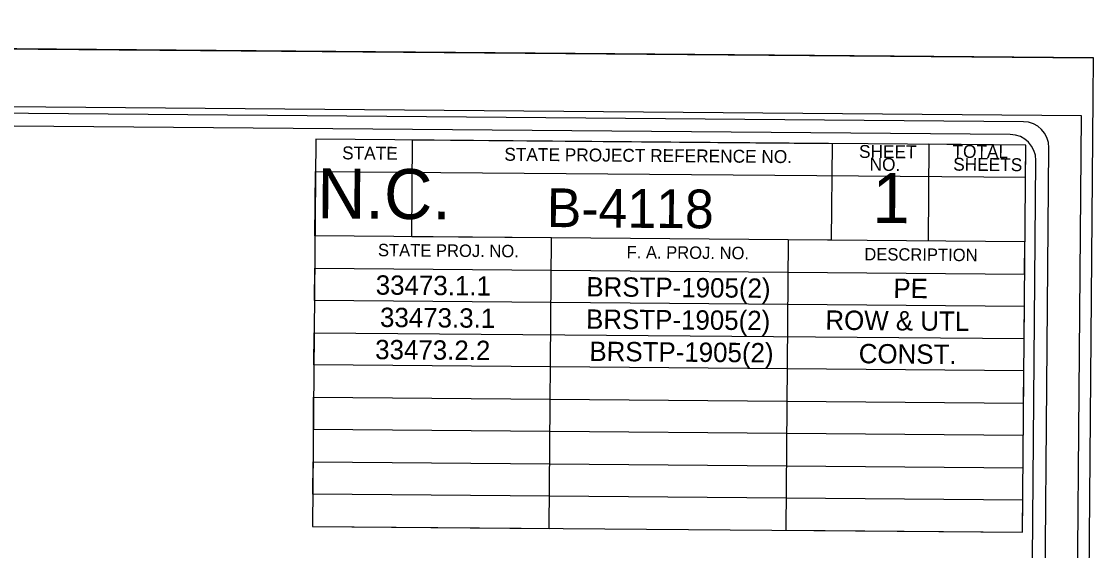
# Model space of a CAD drawing. Extents: x 1379453 to 1387082, y 594364 to 596664.
# Drawn here: x 1382008 to 1382839, y 596182 to 596592 of the extents above; entities that cross this region are included whole.
import ezdxf

# ---------------------------------------------------------------- set-up
doc = ezdxf.new("R2010")
doc.units = 0
for name, color, linetype in [('Sheet Cutting Line CELL', 7, 'Continuous'), ('Sheet Data Field CELL', 7, 'Continuous'), ('Sheet Plot Border Inside CELL', 7, 'Continuous'), ('Sheet Plot Border Outside CELL', 7, 'Continuous'), ('Sheet Title CELL', 7, 'Continuous')]:
    doc.layers.add(name, color=color, linetype=linetype)

msp = doc.modelspace()

# ---------------------------------------------------------------- linework, layer by layer
at = {"layer": 'Sheet Cutting Line CELL'}
msp.add_line((1379471.02, 596592.12), (1382838.9, 596563.91), dxfattribs=at)
at = {"layer": 'Sheet Plot Border Inside CELL'}
msp.add_lwpolyline([(1379478.96, 594436.88), (1382811.85, 594408.96), (1382829.53, 596519.08), (1379496.64, 596547.01)], close=True, dxfattribs=at)
at = {"layer": 'Sheet Plot Border Outside CELL'}
msp.add_lwpolyline([(1382838.9, 596563.91), (1379471.02, 596592.12), (1379452.59, 594392.22), (1382820.47, 594364.01)], close=True, dxfattribs=at)
at = {"layer": 'Sheet Title CELL'}
for points in [[(1382784.51, 596514.36), (1379824.56, 596539.18)], [(1382774.4, 596504.45), (1379934.53, 596528.24)], [(1382233.84, 596200.99), (1382783.82, 596196.38), (1382784.03, 596221.36), (1382234.05, 596225.99), (1382234.26, 596250.96), (1382784.24, 596246.35), (1382784.45, 596271.35), (1382234.49, 596275.96), (1382234.68, 596300.99), (1382784.66, 596296.38), (1382784.87, 596321.38), (1382234.89, 596325.98), (1382235.1, 596350.96), (1382785.08, 596346.38), (1382785.29, 596371.35), (1382235.31, 596375.96), (1382235.52, 596400.96), (1382785.5, 596396.35), (1382785.71, 596421.37), (1382235.72, 596425.98), (1382236.14, 596475.98), (1382786.12, 596471.37), (1382786.33, 596496.37), (1382236.35, 596500.95), (1382233.84, 596200.99), (1382417.13, 596199.43), (1382419.02, 596424.42), (1382310.72, 596425.33), (1382311.35, 596500.35), (1382636.36, 596497.6), (1382635.71, 596422.63), (1382602.31, 596422.91), (1382600.43, 596197.92), (1382783.82, 596196.38), (1382786.33, 596496.37), (1382711.34, 596497), (1382710.73, 596422)], [(1382787.06, 594434.29), (1382804.32, 596494.2)], [(1382780.24, 594814.34), (1382794.23, 596484.3)]]:
    msp.add_lwpolyline(points, dxfattribs=at)
for centre in [(1382784.33, 596494.48), (1382774.24, 596484.56)]:
    msp.add_arc(centre, 20, 359.52002, 89.52002, dxfattribs=at)

# ---------------------------------------------------------------- texts
at = {"layer": 'Sheet Data Field CELL'}
for s, height, p in [('B-4118', 30, (1382415.21, 596432.85)), ('33473.1.1 ', 15, (1382282.75, 596380.49)), ('BRSTP-1905(2) ', 15, (1382445.91, 596379.12)), ('PE', 15, (1382683.77, 596377.94)), ('33473.3.1', 15, (1382286.05, 596355.43)), ('BRSTP-1905(2) ', 15, (1382445.7, 596354.09)), ('ROW & UTL', 15, (1382631.09, 596353.27)), ('33473.2.2', 15, (1382282.29, 596330.49)), ('BRSTP-1905(2)', 15, (1382448.26, 596329.1)), ('CONST.', 15, (1382656.93, 596327.35))]:
    msp.add_text(s, height=height, rotation=359.52002, dxfattribs=at).set_placement(p)
at = {"layer": 'Sheet Title CELL'}
for s, height, p in [('STATE', 10, (1382256.72, 596485.31)), ('SHEET', 10, (1382657.15, 596486.43)), ('TOTAL', 10, (1382729.55, 596486.55)), ('STATE PROJECT REFERENCE NO.', 9.9996, (1382382.42, 596484.23)), ('NO.', 10, (1382665.36, 596476.48)), ('SHEETS', 10, (1382730.14, 596476.54)), ('N.C.', 38.7, (1382237.34, 596439.67)), ('1', 38.7, (1382667.52, 596436.06)), ('STATE PROJ. NO.', 9.6, (1382284.49, 596410.27)), ('F. A. PROJ. NO.', 9.6, (1382477.09, 596408.66)), ('DESCRIPTION', 9.6, (1382661.28, 596407.09))]:
    msp.add_text(s, height=height, rotation=359.52002, dxfattribs=at).set_placement(p)

doc.saveas('drawing.dxf')
